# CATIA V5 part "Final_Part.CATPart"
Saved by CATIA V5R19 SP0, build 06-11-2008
Bounding box of the stored display mesh (mm): x 114.826 to 851.192, y -88.967 to 51.033, z -30.833 to 23.79
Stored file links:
  C:\Documents and Settings\dpv\Desktop\SL9_test_14th_august\everything_done\Final_Part.CATPart
  C:\Program Files\Dassault Systemes\Strip Layout Design\intel_a\resources\graphic\Template\Strip_Construction.CATPart
  C:\Program Files\Dassault Systemes\Strip Layout Design\intel_a\resources\graphic\Template\StripLayout_Construc.CATProduct
  \\drq32plp\temp\R18_HQJ_Tool.CATPart
  C:\Documents and Settings\dpv\Desktop\SL9_test_14th_august\everything_done\Strip_Construction.CATPart
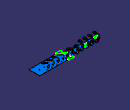
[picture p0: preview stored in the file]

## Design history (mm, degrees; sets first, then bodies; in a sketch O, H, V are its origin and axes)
TTRSSet1
Set1 "PositioningPunches"
  DatumCurve1 "Punch_Contour: Station1"
  DatumCurve2 "Punch_Contour: Station3:3rd"
  DatumCurve3 "Punch_Contour: Station6:6th"
  DatumCurve4 "Punch_Contour: Station7:7th"
  DatumCurve5 "Punch_Contour: Station8:8th"
  Circle1 "Punch_Contour: Station8:8th": stored without definition
  Circle2 "Punch_Contour: Station9:9th": stored without definition
Body1 (main body)
Body2 "Final Strip"
  Solid1: linked copy from another document
  Body3 "Isolated"
    Solid2: solid without history
  Assemble1 "Isolated From Strip": tool Body3
  Body4 "Isolated"
    Solid3: solid without history
  Assemble2 "Isolated From Strip": tool Body4
  Body5 "Isolated"
    Solid4: solid without history
  Assemble3 "Isolated From Strip": tool Body5
  Body6 "Isolated"
    Solid5: solid without history
  Assemble4 "Isolated From Strip": tool Body6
